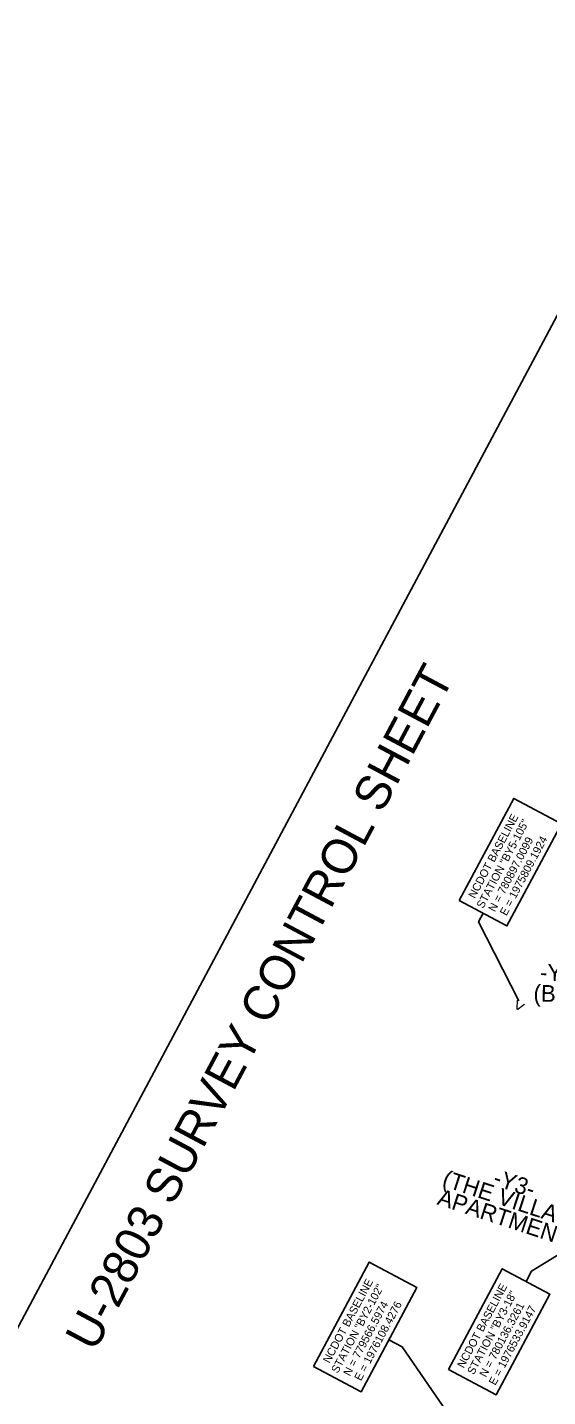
# Model space of a CAD drawing. Extents: x 1970823 to 1988115, y 770601 to 786368.
# Drawn here: x 1974849 to 1976409, y 779627 to 783732 of the extents above; entities that cross this region are included whole.
import ezdxf

# ---------------------------------------------------------------- set-up
doc = ezdxf.new("R2010")
doc.units = 0
for name, color, linetype in [('CTL Sheet Border CELL', 7, 'Continuous'), ('CTL Sheet Text', 7, 'Continuous'), ('CTL Supplemental Horizontal and Vertical Text', 7, 'Continuous'), ('Default', 7, 'Continuous'), ('Old_Level_57', 7, 'Continuous'), ('Sheet Data Field CELL', 7, 'Continuous')]:
    doc.layers.add(name, color=color, linetype=linetype)

msp = doc.modelspace()

# ---------------------------------------------------------------- linework, layer by layer
at = {"layer": 'CTL Sheet Border CELL'}
msp.add_lwpolyline([(1977401.8, 784679.3), (1973721.3, 777772.6), (1978555.9, 775196.3), (1982236.4, 782102.9)], close=True, dxfattribs=at)
at = {"layer": 'CTL Supplemental Horizontal and Vertical Text'}
for points in [[(1976215.5, 781075.9), (1976202, 781050.6), (1976323, 780813.8)], [(1976344.2, 779972), (1976360.9, 780003.3), (1976505.3, 780092.2)], [(1975932.9, 779797.4), (1975972.3, 779776.4), (1976095.3, 779597.5)]]:
    msp.add_lwpolyline(points, dxfattribs=at)
at = {"layer": 'Default'}
for points in [[(1976144, 781113.9), (1976307.3, 781420.3), (1976450.2, 781344.1), (1976287, 781037.8)], [(1975706.4, 779716.9), (1975873.4, 780030.2), (1976016.4, 779954.1), (1975849.4, 779640.7)], [(1976111.7, 779707.7), (1976272.8, 780010.1), (1976415.7, 779933.9), (1976254.6, 779631.6)]]:
    msp.add_lwpolyline(points, close=True, dxfattribs=at)

# ---------------------------------------------------------------- texts
at = {"layer": 'CTL Sheet Text'}
for s, rotation, p in [('-Y5- SR 1967', 359.0351, (1976385.7, 780874.1)), ('(BPW CLUB RD.)', 359.0351, (1976366.2, 780811.3)), ('(THE VILLAGE', 341.8664, (1976089.7, 780259.4)), ('-Y3-', 341.8664, (1976242.1, 780262.2)), ('APARTMENTS)', 341.8664, (1976075, 780203.8))]:
    msp.add_text(s, height=50, rotation=rotation, dxfattribs=at).set_placement(p)
at = {"layer": 'CTL Supplemental Horizontal and Vertical Text'}
for s, p in [('NCDOT BASELINE', (1976190.6, 781118.4)), ('STATION "BY5-105"', (1976215.4, 781088.4)), ('N = 780897.0099', (1976250.8, 781078.3)), ('E = 1975809.1924', (1976285.3, 781066.6)), ('NCDOT BASELINE', (1975754.9, 779724.9)), ('STATION "BY2-102"', (1975779.7, 779694.9)), ('NCDOT BASELINE', (1976157.2, 779710.2)), ('N = 779566.5974', (1975815.9, 779686.3)), ('E = 1976108.4276', (1975849.1, 779672)), ('STATION "BY3-18"', (1976187.5, 779690.5)), ('N = 780136.3261', (1976224.1, 779682.8)), ('E = 1976533.9147', (1976252.1, 779658.7))]:
    msp.add_text(s, height=24, rotation=61.9471, dxfattribs=at).set_placement(p)
at = {"layer": 'Old_Level_57'}
msp.add_text('>', height=39.1, rotation=241.9613, dxfattribs=at).set_placement((1976313.9, 780820.5))
at = {"layer": 'Sheet Data Field CELL'}
msp.add_text('U-2803 SURVEY CONTROL SHEET', height=104.348, rotation=61.9471, dxfattribs=at).set_placement((1975050.7, 779758))

doc.saveas('drawing.dxf')
